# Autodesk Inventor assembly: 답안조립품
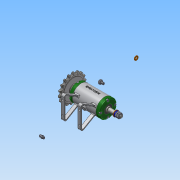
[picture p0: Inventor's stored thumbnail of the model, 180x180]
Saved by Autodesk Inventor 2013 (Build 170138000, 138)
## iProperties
Created: 2016-03
Part Number: 답안조립품
Document SubType Name: Assembly
Designer: Administrator
Author: Administrator
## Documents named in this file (16)
- C:\Users\Administrator\Desktop\460308V1013\답안조립품.iam
- C:\Users\Administrator\Desktop\460308V1013\V벨트풀리.ipt
- C:\Users\Administrator\Desktop\460308V1013\너트 M 8.ipt
- C:\Users\Administrator\Desktop\460308V1013\니플 M 6 x 0.75.ipt
- C:\Users\Administrator\Desktop\460308V1013\베어링 15 x 32 x 9.ipt
- C:\Users\Administrator\Desktop\460308V1013\본체.ipt
- C:\Users\Administrator\Desktop\460308V1013\볼트 M 6 x 8.ipt
- C:\Users\Administrator\Desktop\460308V1013\볼트 M4 x 12.ipt
- C:\Users\Administrator\Desktop\460308V1013\스프로킷.ipt
- C:\Users\Administrator\Desktop\460308V1013\스프링와셔 8.ipt
- C:\Users\Administrator\Desktop\460308V1013\오일 실 15 25 7.ipt
- C:\Users\Administrator\Desktop\460308V1013\와셔 6x11.5.ipt
- C:\Users\Administrator\Desktop\460308V1013\와셔 8x17.ipt
- C:\Users\Administrator\Desktop\460308V1013\축.ipt
- C:\Users\Administrator\Desktop\460308V1013\커버.ipt
- C:\Users\Administrator\Desktop\460308V1013\키 3 x 3 x 12.ipt
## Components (11 placed, 3 different names)
1. V벨트풀리:1 — 각도:1, 각도:2
2. KS B 2023 6002 - 15 x 32 x 9:1
3. KS B 2023 6002 - 15 x 32 x 9:2
4. ISO 4762 M4 x 12:2
5. ISO 4762 M4 x 12:1
6. ISO 4762 M4 x 12:3
7. ISO 4762 M4 x 12:4
8. ISO 4762 M4 x 12:5
9. ISO 4762 M4 x 12:6
10. ISO 4762 M4 x 12:7
11. ISO 4762 M4 x 12:8
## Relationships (2: Angle 2)
- 각도:1 [Angle]: V벨트풀리:1
- 각도:2 [Angle]: V벨트풀리:1
